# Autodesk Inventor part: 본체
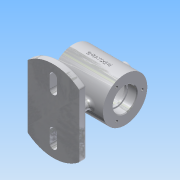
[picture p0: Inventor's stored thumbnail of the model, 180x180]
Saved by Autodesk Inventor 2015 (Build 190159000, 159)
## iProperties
Created: 2017-12
Part Number: 본체
Material: 알루미늄 6061
Document SubType Name: Modeling
Designer: Administrator
Density: 2.7 g/cm^3
Appearance: 알루미늄 - 평지
Mass: 465.72 g
Surface Area: 486.417 cm^2
Volume: 172.489 cm^3
Author: Administrator
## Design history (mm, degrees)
sketch "스케치5"
  geometry: L1 (35, -42.426)-(35, 42.426); L2 (-35, 42.426)-(-35, -42.426); A1 r 55 centre (0, 0) between (35, 42.426) and (-35, 42.426); A2 r 55 centre (0, 0) between (-35, -42.426) and (35, -42.426); 1 further point
  constraints: 4 end point, 4 point on circle, 2 centre point, 2 vertical, 1 coincident
  dimensions: "d1" = 35 distance from line of point (0, 0) L1; "d2" = 70 distance between parallel lines of L2 L1; "d3" = 55 radius of A2; "d4" = 55 radius of A1
extrude "돌출1" new body sketch "스케치5" distance "d5" = 10; taper "d6" = 0 deg
fillet "모깎기1" dims "d7" = 3
fillet "모깎기2" dims "d8" = 3
sketch "스케치6"
  geometry: C1 r 30 at (62, 0); 1 further point
  constraints: 1 centre point, 1 horizontal alignment
  dimensions: "d9" = 60 diameter of C1; "d10" = 62 distance of point (0, 0) C1.centre
extrude "돌출2" join sketch "스케치6" stored distance "d11" = 70; taper "d12" = 0 deg
node "작업 평면1"
sketch "스케치7"
  geometry: C1 r 8 at (0, 0); 1 further point
  constraints: 1 centre point, 1 coincident
  dimensions: "d14" = 16 diameter of C1
extrude "돌출3" join sketch "스케치7" distance "d15" = 37; taper "d16" = 0 deg
fillet "모깎기3" dims "d17" = 3
sketch "스케치9"
  geometry: L1 (-35, 78)-(-23.3, 78); L2 (-23, 77.7)-(-23, 76); L3 (-23, 76)-(-20, 76); L4 (-20, 76)-(-20, 84); L5 (-17, 87)-(17, 87); L6 (20, 84)-(20, 76); L7 (20, 76)-(23, 76); L8 (23, 76)-(23, 77.7); L9 (23.3, 78)-(35, 78); L10 (-35, 62)-(35, 62); L11 (-35, 92)-(-35, 32) reference; L12 (35, 32)-(35, 92) reference; L13 (-35, 78)-(-35, 62); L14 (35, 78)-(35, 62); A1 r 3 centre (17, 84) between (20, 84) and (17, 87); A2 r 3 centre (-17, 84) between (-17, 87) and (-20, 84); A3 r 0.3 centre (-23.3, 77.7) between (-23, 77.7) and (-23.3, 78); A4 r 0.3 centre (23.3, 77.7) between (23.3, 78) and (23, 77.7); 5 further points
  constraints: 24 end point, 10 point on line, 8 perpendicular, 8 point on circle, 8 tangent, 4 centre point, 2 equal radius, 2 horizontal, 2 midpoint, 1 collinear, 1 vertical
  dimensions: "d18" = 62 distance from line of point (0, 0) L10; "d19" = 16 distance between parallel lines of L10 L1; "d20" = 14 distance between parallel lines of L10 L3; "d21" = 25 distance between parallel lines of L10 L5; "d22" = 14 distance between parallel lines of L10 L7; "d23" = 16 distance between parallel lines of L10 L9; "d24" = 12 distance between parallel lines of L2 L11; "d25" = 12 distance between parallel lines of L12 L8; "d26" = 3 distance of L6.end L7.end; "d28" = 40 distance between parallel lines of L6 L4; "d30" = 3 radius of A1; "d31" = 0.3 radius of A3
revolve "회전1" stored, may be unused: angle "d29" = 90 deg
chamfer "모따기1" distance "d32" = 1; stored, may be unused: second distance "d33" = 2, angle "d34" = 45 deg
sketch "스케치10" dims "d35" = 46
  geometry: C1 r 30 at (0, 0) reference; C2 r 17 at (0, 0) reference; 3 further points
  constraints: 2 vertical alignment, 1 coincident, 2 other
hole "구멍1" sketch "스케치10" at (0, 23) diameter "d36" = 3.459; stored, may be unused: countersink angle "d40" = 90 deg, drill point angle "d42" = 118 deg; dims "d37" = 8, "d38" = 4, "d39" = 2, "d41" = 10
node "작업 평면2"
sketch "스케치11"
  geometry: C1 r 8 at (0, 0) reference; C2 r 4 at (0, 0)
  constraints: 1 centre point, 1 coincident
  dimensions: "d46" = 8 diameter of C2
extrude "돌출4" cut sketch "스케치11" distance "d47" = 37; taper "d48" = 0 deg
chamfer "모따기2" distance "d49" = 1; stored, may be unused: second distance "d50" = 2, angle "d51" = 45 deg
sketch "스케치12"
  geometry: L1 (-15, 0)-(15, 0); L2 (-15, -5)-(15, -5); L3 (15, 5)-(-15, 5); L4 (0, 40)-(0, 24); L5 (-5, 40)-(-5, 24); L6 (5, 24)-(5, 40); A1 r 52 centre (0, 0) between (32, 40.988) and (-32, 40.988) reference; A2 r 52 centre (0, 0) between (-32, -40.988) and (32, -40.988) reference; A3 r 5 centre (-15, 0) between (-15, 5) and (-15, -5); A4 r 5 centre (15, 0) between (15, -5) and (15, 5); A5 r 5 centre (0, 40) between (5, 40) and (-5, 40); A6 r 5 centre (0, 24) between (-5, 24) and (5, 24); 1 further point
  constraints: 16 end point, 8 point on circle, 8 tangent, 4 centre point, 2 midpoint, 2 parallel, 1 horizontal, 1 vertical, 1 vertical alignment
  dimensions: "d52" = 30 distance of L1.start L1.end; "d53" = 5 radius of A3; "d54" = 16 distance of L4.start L4.end; "d55" = 24 distance of A2.centre L4.end; "d56" = 5 radius of A5
extrude "돌출5" join sketch "스케치12" distance "d57" = 52; taper "d58" = 0 deg
revolve "회전2" stored, may be unused: angle "d59" = 90 deg
extrude "돌출6" cut sketch "스케치12" distance "d60" = 52; taper "d61" = 0 deg
fillet "모깎기4" dims "d62" = 5
node "작업 평면3"
sketch "스케치13"
  geometry: L1 (-35, 92)-(-35, 32) reference; L2 (-35, 92)-(35, 92) reference; 2 further points
  constraints: 1 other
  dimensions: "d64" = 30 distance from line of L2 point (0, 62); "d65" = 35 distance from line of L1 point (0, 62)
feature "엠보싱1" sketch "스케치13" dims "d1" = 35, "d2" = 70, "d3" = 55, "d4" = 55, "d66" = 0.5, "d67" = 0
node "솔리드1"
pattern_circular "원형 패턴1" dims angle "d44" = 360 deg
mirror "대칭1"
mirror "대칭2"
other parameters: "d13" = 62, "d63" = 69.5
